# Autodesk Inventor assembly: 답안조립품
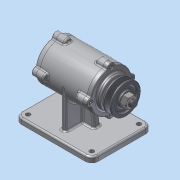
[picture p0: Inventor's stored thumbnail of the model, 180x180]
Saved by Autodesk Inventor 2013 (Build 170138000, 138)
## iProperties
Created: 2015-12
Part Number: 답안조립품
Document SubType Name: Assembly
Designer: dgall
Author: dgall
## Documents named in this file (11)
- C:\Users\dgall\Desktop\451207V1016\답안조립품.iam
- C:\Users\dgall\Desktop\451207V1016\1-본체.ipt
- C:\Users\dgall\Desktop\451207V1016\커버2.ipt
- C:\Users\dgall\Desktop\451207V1016\베어링 6204.ipt
- C:\Users\dgall\Desktop\451207V1016\커버.ipt
- C:\Users\dgall\Desktop\451207V1016\축.ipt
- C:\Users\dgall\Desktop\451207V1016\키(4 x 4 x 12).ipt
- C:\Users\dgall\Desktop\451207V1016\오일실.ipt
- C:\Users\dgall\Desktop\451207V1016\V-벨트풀리.ipt
- C:\Users\dgall\Desktop\451207V1016\너트 M12x1.25.ipt
- C:\Users\dgall\Desktop\451207V1016\볼트 M4 x 12.ipt
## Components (7 placed, 6 different names)
1. 1-본체:1
2. KS B 2023 6204 - 20 x 47 x 14:1
3. KS B 2023 6204 - 20 x 47 x 14:2
4. KS B 1311 (I) 4 x 4 x 12:1
5. KS B 2804 D D - 20 32 8:1
6. V-벨트풀리:1
7. KS B 1012 클래스 1 일반 - 미터 M12x1.25:1
